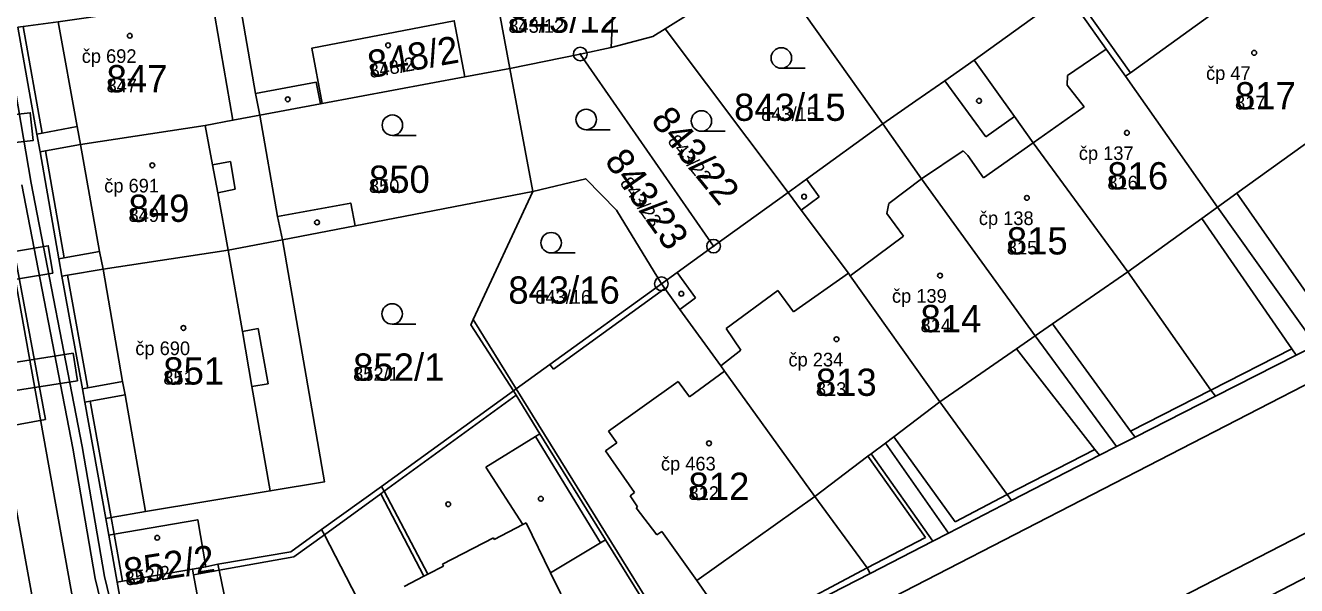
# Model space of a CAD drawing. Extents: x -763628 to -761565, y -976033 to -973833.
# Drawn here: x -762085.7 to -761992.5, y -974693.2 to -974652.1 of the extents above; entities that cross this region are included whole.
import ezdxf

# ---------------------------------------------------------------- set-up
doc = ezdxf.new("R2010")
doc.units = 0
for name, color, linetype in [('KN_cisla parcel 1000', 7, 'Continuous'), ('KN_cisla parcel 500', 7, 'Continuous'), ('KN_cisla popisna 500', 7, 'Continuous'), ('KN_hranice parcel', 7, 'Continuous'), ('KN_vecna bremena', 7, 'Continuous'), ('KN_vnitrni kresba parcel', 7, 'Continuous'), ('KN_znacky bodu BP', 7, 'Continuous'), ('KN_znacky budov', 7, 'Continuous'), ('KN_znacky kultur', 7, 'Continuous')]:
    doc.layers.add(name, color=color, linetype=linetype)

msp = doc.modelspace()

# ---------------------------------------------------------------- linework, layer by layer
at = {"layer": 'KN_hranice parcel'}
for p, q in [((-762042.7, -974653.77), (-762042.3, -974644.72)), ((-762051.82, -974646.23), (-762050.13, -974655.3)), ((-762038.76, -974652.39), (-762031.13, -974647.62)), ((-762022.79, -974659.35), (-762031.13, -974647.62)), ((-762011.38, -974651.3), (-762016.09, -974654.68)), ((-762038.76, -974652.39), (-762029.73, -974664.39)), ((-762044.98, -974654.24), (-762042.7, -974653.77)), ((-762050.13, -974655.3), (-762044.98, -974654.24)), ((-762044.98, -974654.24), (-762035.2, -974668.33)), ((-762053.45, -974655.92), (-762050.13, -974655.3)), ((-762048.46, -974664.33), (-762050.13, -974655.3)), ((-762063.89, -974657.87), (-762053.45, -974655.92)), ((-762068.48, -974658.73), (-762064.03, -974657.9)), ((-762064.03, -974657.9), (-762063.89, -974657.87)), ((-762061.49, -974666.84), (-762048.46, -974664.33)), ((-762029.73, -974664.39), (-762035.2, -974668.33)), ((-761991.04, -974675.58), (-761998.26, -974665.47)), ((-762066.81, -974667.86), (-762061.49, -974666.84)), ((-762079.77, -974688.31), (-762079.55, -974689.53)), ((-762079.55, -974689.53), (-762078.93, -974692.97)), ((-762071.54, -974691.66), (-762072.42, -974691.84))]:
    msp.add_line(p, q, dxfattribs=at)
for points in [[(-762064.03, -974657.9), (-762064.33, -974656.31), (-762068.78, -974657.14), (-762070.06, -974649.78)], [(-761998.26, -974665.47), (-762004.99, -974655.87), (-762006.41, -974653.88), (-762008.25, -974651.3), (-762009.31, -974649.82)], [(-762086.22, -974652.28), (-762085.82, -974652.22), (-762083.26, -974651.87), (-762074.05, -974650.56)], [(-762063.89, -974657.87), (-762064.65, -974653.8), (-762054.22, -974651.8), (-762053.45, -974655.92)], [(-762086.22, -974652.28), (-762084.82, -974660.12), (-762084.59, -974661.41)], [(-762042.7, -974653.77), (-762039.65, -974652.95), (-762038.76, -974652.39)], [(-762016.09, -974654.68), (-762018.24, -974656.21), (-762020.37, -974657.66), (-762022.79, -974659.35)], [(-761998.41, -974679.34), (-761998.73, -974678.89), (-762004.84, -974670.21), (-762011.77, -974660.75), (-762013.14, -974658.83), (-762016.09, -974654.68)], [(-761998.26, -974665.47), (-761996.84, -974664.44), (-761987.89, -974658.01), (-761987.24, -974657.54)], [(-762084.59, -974661.41), (-762084.2, -974661.34), (-762081.62, -974660.88), (-762072.47, -974659.48), (-762070.44, -974659.1), (-762068.48, -974658.73)], [(-762061.49, -974666.84), (-762061.81, -974665.17), (-762067.17, -974666.15), (-762068.48, -974658.73)], [(-762022.79, -974659.35), (-762028.4, -974663.42), (-762029.73, -974664.39)], [(-762005.65, -974683.02), (-762011.63, -974674.91), (-762019.95, -974663.38), (-762022.79, -974659.35)], [(-762084.59, -974661.41), (-762083.2, -974669.25), (-762082.98, -974670.53)], [(-762039.03, -974671.09), (-762042.33, -974665.68), (-762044.58, -974663.39), (-762048.46, -974664.33)], [(-762049.87, -974678.94), (-762053, -974674.09), (-762052.83, -974673.72), (-762048.46, -974664.33)], [(-762013.35, -974686.98), (-762013.67, -974686.55), (-762018.62, -974679.75), (-762025.18, -974670.5), (-762025.3, -974670.32), (-762028.79, -974665.68), (-762029.73, -974664.39)], [(-762082.98, -974670.53), (-762082.58, -974670.46), (-762079.97, -974670.02), (-762070.79, -974668.63), (-762066.81, -974667.86)], [(-762079.77, -974688.31), (-762079.37, -974688.24), (-762076.85, -974687.79), (-762067.71, -974686.28), (-762063.73, -974685.61), (-762066.81, -974667.86)], [(-762035.2, -974668.33), (-762037.86, -974670.25), (-762039.03, -974671.09)], [(-762082.98, -974670.53), (-762081.48, -974678.79), (-762081.31, -974679.78), (-762079.77, -974688.31)], [(-762039.03, -974671.09), (-762047.21, -974677.01), (-762049.68, -974678.8), (-762049.87, -974678.94)], [(-762023.72, -974692.34), (-762023.94, -974691.92), (-762027.78, -974686.7), (-762034.39, -974677.51), (-762034.68, -974677.1), (-762037.68, -974672.97), (-762038.78, -974671.43), (-762039.03, -974671.09)], [(-761998.41, -974679.34), (-761992.49, -974676.32), (-761991.04, -974675.58)], [(-762049.87, -974678.94), (-762059.55, -974685.95), (-762063.94, -974689.12)], [(-762043.13, -974689.86), (-762047.93, -974682.09), (-762049.67, -974679.26), (-762049.87, -974678.94)], [(-762005.65, -974683.02), (-762004.3, -974682.34), (-761998.41, -974679.34)], [(-762013.35, -974686.98), (-762006.91, -974683.67), (-762005.65, -974683.02)], [(-762023.72, -974692.34), (-762019.12, -974689.96), (-762017.98, -974689.37), (-762013.35, -974686.98)], [(-762079.55, -974689.53), (-762079.15, -974689.46), (-762073.02, -974688.39), (-762072.42, -974691.84)], [(-762063.94, -974689.12), (-762066.21, -974690.76), (-762071.54, -974691.66)], [(-762054.13, -974708.07), (-762054.27, -974707.8), (-762060.69, -974695.41), (-762061.34, -974694.14), (-762063.74, -974689.5), (-762063.94, -974689.12)], [(-762051.03, -974706.45), (-762051.16, -974706.19), (-762053.23, -974702.36), (-762046.78, -974699.11), (-762046.11, -974699.33), (-762044.61, -974698.55), (-762044.05, -974696.94), (-762044.94, -974695.52), (-762045.68, -974695.31), (-762047.15, -974692.3), (-762043.49, -974690.08), (-762043.13, -974689.86)], [(-762037.3, -974699.3), (-762037.44, -974699.03), (-762043.13, -974689.86)], [(-762072.42, -974691.84), (-762073.41, -974692.01), (-762078.53, -974692.9), (-762078.93, -974692.97)], [(-762063.09, -974712.69), (-762063.3, -974712.28), (-762065.03, -974709.22), (-762069.14, -974700.49), (-762069.74, -974699.23), (-762070.18, -974698.29), (-762071.45, -974692.1), (-762071.54, -974691.66)], [(-762078.93, -974692.97), (-762078.32, -974696.37), (-762076.4, -974707.16), (-762076.22, -974708.14), (-762074.96, -974715.24), (-762071.48, -974717.01)], [(-762037.3, -974699.3), (-762034.91, -974698.07), (-762033.35, -974697.27), (-762023.72, -974692.34)]]:
    msp.add_lwpolyline(points, dxfattribs=at)
at = {"layer": 'KN_vecna bremena'}
for points in [[(-762089.51, -974682.03), (-762084.2, -974681.04), (-762095.27, -974621.68)], [(-761988.76, -974691.06), (-762016.29, -974705.31), (-762021.52, -974708.2), (-762033, -974714.19), (-762037.98, -974716.84), (-762040.66, -974717.95), (-762050.35, -974722.91), (-762064.2, -974729.69), (-762065.07, -974729.71), (-762065.78, -974729.85), (-762066.52, -974728.18), (-762070.83, -974719.24), (-762071.18, -974718.59), (-762071.95, -974717.95), (-762072.56, -974717.54), (-762074.56, -974716.2), (-762075.21, -974715.43), (-762078.94, -974696.4), (-762079.87, -974692.57), (-762081.5, -974683.02), (-762085.24, -974663.7), (-762087.15, -974652.51)], [(-762091.32, -974661.27), (-762085.08, -974660.57), (-762085.31, -974658.55), (-762091.67, -974659.25)], [(-762085.92, -974663.82), (-762082.18, -974683.14), (-762080.55, -974692.71), (-762079.62, -974696.54), (-762075.87, -974715.75), (-762075.04, -974716.72), (-762073.29, -974717.89), (-762072.37, -974718.51), (-762071.74, -974719.05), (-762071.45, -974719.56), (-762067.16, -974728.48), (-762066.35, -974730.3), (-762066.45, -974730.92), (-762067.22, -974732.38), (-762067.56, -974735.13), (-762067.5, -974735.7), (-762065.34, -974740.35), (-762064.59, -974741.77), (-762063.72, -974743.22), (-762062.71, -974745.45), (-762062.16, -974747.4), (-762060.52, -974750.71)], [(-762087.37, -974670.93), (-762083.66, -974670.31), (-762083.99, -974668.3), (-762087.77, -974668.93)], [(-762087.84, -974679.14), (-762081.85, -974678.2), (-762082.17, -974676.19), (-762088.2, -974677.13)], [(-762086.79, -974697), (-762085.28, -974704.55), (-762084.55, -974708.69), (-762081.89, -974721.59), (-762079.13, -974720.73), (-762076.95, -974720.04), (-762076.45, -974723.59), (-762074.35, -974723.29), (-762075.04, -974718.74), (-762075.21, -974717.28), (-762080.29, -974718.87), (-762082.47, -974708.29), (-762083.02, -974705.18), (-762076.93, -974704.19), (-762077.29, -974702.18), (-762083.39, -974703.18), (-762084.71, -974696.6), (-762086.83, -974684.87)]]:
    msp.add_lwpolyline(points, dxfattribs=at)
at = {"layer": 'KN_vnitrni kresba parcel'}
for p, q in [((-762092.3, -974638.03), (-762078.65, -974713.9)), ((-762004.63, -974655.61), (-761994.48, -974648.27)), ((-762071.99, -974650.16), (-762070.44, -974659.1)), ((-762007.89, -974651.05), (-762004.63, -974655.61)), ((-762081.86, -974659.56), (-762083.26, -974651.87)), ((-762084.43, -974660.05), (-762085.82, -974652.22)), ((-762009.24, -974655.82), (-762006.41, -974653.88)), ((-762009.28, -974656.52), (-762009.24, -974655.82)), ((-762004.63, -974655.61), (-762004.99, -974655.87)), ((-762015.24, -974660.32), (-762018.24, -974656.21)), ((-762008.02, -974658.1), (-762009.28, -974656.52)), ((-762068.48, -974658.73), (-762068.78, -974657.14)), ((-762011.77, -974660.75), (-762008.02, -974658.1)), ((-762084.43, -974660.05), (-762081.86, -974659.56)), ((-762081.62, -974660.88), (-762081.86, -974659.56)), ((-762071.94, -974662.37), (-762072.47, -974659.48)), ((-762013.14, -974658.83), (-762015.24, -974660.32)), ((-762084.82, -974660.12), (-762084.43, -974660.05)), ((-762082.81, -974669.18), (-762084.2, -974661.34)), ((-762080.23, -974668.72), (-762081.62, -974660.88)), ((-762016.9, -974661.33), (-762019.95, -974663.38)), ((-762016.9, -974661.33), (-762016.57, -974661.69)), ((-762015.41, -974663.33), (-762011.77, -974660.75)), ((-762071.94, -974662.37), (-762070.63, -974662.13)), ((-762071.56, -974664.41), (-762071.94, -974662.37)), ((-762070.63, -974662.13), (-762070.29, -974664.14)), ((-762016.57, -974661.69), (-762015.41, -974663.33)), ((-762071.56, -974664.41), (-762070.29, -974664.14)), ((-762027.46, -974664.72), (-762028.4, -974663.42)), ((-762019.95, -974663.38), (-762022.35, -974665.21)), ((-762070.79, -974668.63), (-762071.56, -974664.41)), ((-762028.79, -974665.68), (-762027.46, -974664.72)), ((-761989.89, -974674.41), (-761996.84, -974664.44)), ((-762070.28, -974718.91), (-761967.13, -974665.79)), ((-762022.35, -974665.21), (-762022.49, -974665.93)), ((-762022.49, -974665.93), (-762021.27, -974667.6)), ((-761998.26, -974665.47), (-761999.41, -974666.29)), ((-762066.81, -974667.86), (-762067.17, -974666.15)), ((-761999.41, -974666.29), (-762004.84, -974670.21)), ((-761999.41, -974666.29), (-761992.81, -974675.87)), ((-762021.27, -974667.6), (-762025.18, -974670.5)), ((-762080.23, -974668.72), (-762082.81, -974669.18)), ((-762079.97, -974670.02), (-762080.23, -974668.72)), ((-762069.75, -974674.58), (-762070.79, -974668.63)), ((-762082.81, -974669.18), (-762083.2, -974669.25)), ((-762081.09, -974678.72), (-762082.58, -974670.46)), ((-762078.53, -974678.26), (-762079.97, -974670.02)), ((-762036.52, -974672.11), (-762037.86, -974670.25)), ((-762025.3, -974670.32), (-762029.35, -974673.14)), ((-762010.34, -974674.02), (-762004.84, -974670.21)), ((-762038.78, -974671.43), (-762046.93, -974677.34)), ((-762030.5, -974671.58), (-762034.28, -974674.38)), ((-762029.35, -974673.14), (-762030.5, -974671.58)), ((-762037.68, -974672.97), (-762036.52, -974672.11)), ((-762069.75, -974674.58), (-762068.6, -974674.38)), ((-762068.6, -974674.38), (-762067.86, -974678.42)), ((-762052.83, -974673.72), (-762049.68, -974678.8)), ((-762034.28, -974674.38), (-762033.21, -974675.97)), ((-762011.63, -974674.91), (-762010.34, -974674.02)), ((-762004.63, -974681.89), (-762010.34, -974674.02)), ((-762069.05, -974678.62), (-762069.75, -974674.58)), ((-762012.99, -974675.85), (-762011.63, -974674.91)), ((-762033.21, -974675.97), (-762034.68, -974677.1)), ((-762012.99, -974675.85), (-762018.62, -974679.75)), ((-762007.24, -974683.24), (-762012.99, -974675.85)), ((-761998.73, -974678.89), (-761992.81, -974675.87)), ((-761992.81, -974675.87), (-761992.49, -974676.32)), ((-762047.21, -974677.01), (-762046.93, -974677.34)), ((-762034.39, -974677.51), (-762036.97, -974679.38)), ((-762081.09, -974678.72), (-762081.48, -974678.79)), ((-762078.53, -974678.26), (-762081.09, -974678.72)), ((-762078.35, -974679.24), (-762078.53, -974678.26)), ((-762067.86, -974678.42), (-762069.05, -974678.62)), ((-762067.71, -974686.28), (-762069.05, -974678.62)), ((-762049.68, -974678.8), (-762037.19, -974698.9)), ((-762037.81, -974678.26), (-762042.9, -974681.91)), ((-762036.97, -974679.38), (-762037.81, -974678.26)), ((-762004.63, -974681.89), (-761998.73, -974678.89)), ((-762080.91, -974679.71), (-762081.31, -974679.78)), ((-762078.35, -974679.24), (-762080.91, -974679.71)), ((-762079.37, -974688.24), (-762080.91, -974679.71)), ((-762076.85, -974687.79), (-762078.35, -974679.24)), ((-762059.36, -974686.31), (-762049.67, -974679.26)), ((-762021.99, -974682.31), (-762018.62, -974679.75)), ((-762042.9, -974681.91), (-762042.29, -974682.75)), ((-762004.3, -974682.34), (-762004.63, -974681.89)), ((-762051.9, -974684.54), (-762048.26, -974682.29)), ((-762048.26, -974682.29), (-762047.93, -974682.09)), ((-762043.49, -974690.08), (-762048.26, -974682.29)), ((-762042.29, -974682.75), (-762043.13, -974683.33)), ((-762023.64, -974683.56), (-762022.6, -974682.77)), ((-762022.6, -974682.77), (-762021.99, -974682.31)), ((-762017.98, -974689.37), (-762022.6, -974682.77)), ((-762021.99, -974682.31), (-762017.49, -974688.55)), ((-762043.13, -974683.33), (-762040.99, -974686.4)), ((-762027.78, -974686.7), (-762023.88, -974683.74)), ((-762023.64, -974683.56), (-762023.88, -974683.74)), ((-762023.88, -974683.74), (-762019.67, -974689.69)), ((-762019.12, -974689.96), (-762023.64, -974683.56)), ((-762013.67, -974686.55), (-762007.24, -974683.24)), ((-762007.24, -974683.24), (-762006.91, -974683.67)), ((-762049.2, -974688.75), (-762051.9, -974684.54)), ((-762063.74, -974689.5), (-762059.61, -974686.49)), ((-762059.61, -974686.49), (-762059.36, -974686.31)), ((-762059.61, -974686.49), (-762056.44, -974692.53)), ((-762059.55, -974685.95), (-762059.36, -974686.31)), ((-762059.36, -974686.31), (-762056.16, -974692.39)), ((-762040.99, -974686.4), (-762041.33, -974686.64)), ((-762013.67, -974686.55), (-762017.49, -974688.55)), ((-761987.98, -974687.41), (-762064.87, -974726.96)), ((-762041.33, -974686.64), (-762040.77, -974687.44)), ((-762040.77, -974687.44), (-762040.89, -974687.53)), ((-762040.89, -974687.53), (-762039.36, -974689.51)), ((-762036.43, -974692.86), (-762027.78, -974686.7)), ((-762079.37, -974688.24), (-762079.15, -974689.46)), ((-762051.28, -974689.84), (-762049.2, -974688.75)), ((-762048.95, -974688.62), (-762049.2, -974688.75)), ((-762047.15, -974692.3), (-762048.95, -974688.62)), ((-762039.36, -974689.51), (-762039, -974689.25)), ((-762039, -974689.25), (-762036.43, -974692.86)), ((-762079.15, -974689.46), (-762078.53, -974692.9)), ((-762065.97, -974691.12), (-762063.74, -974689.5)), ((-762051.35, -974689.72), (-762055.07, -974691.66)), ((-762051.28, -974689.84), (-762051.35, -974689.72)), ((-762019.67, -974689.69), (-762023.94, -974691.92)), ((-762071.45, -974692.1), (-762065.97, -974691.12)), ((-762073.33, -974692.44), (-762073.41, -974692.01)), ((-762073.33, -974692.44), (-762071.45, -974692.1)), ((-762056.16, -974692.39), (-762055.01, -974691.79)), ((-762055.07, -974691.66), (-762055.01, -974691.79)), ((-762023.94, -974691.92), (-762033.53, -974697.01)), ((-762072.79, -974695.38), (-762073.33, -974692.44)), ((-762056.44, -974692.53), (-762057.9, -974693.29)), ((-762056.16, -974692.39), (-762056.44, -974692.53)), ((-762036.43, -974692.86), (-762033.53, -974697.01))]:
    msp.add_line(p, q, dxfattribs=at)
at = {"layer": 'KN_znacky bodu BP'}
for centre, radius in [((-762044.98, -974654.24), 0.5), ((-762044.98, -974654.24), 0.0303), ((-762035.2, -974668.33), 0.5), ((-762035.2, -974668.33), 0.0303), ((-762039.03, -974671.09), 0.5), ((-762039.03, -974671.09), 0.0303)]:
    msp.add_circle(centre, radius, dxfattribs=at)
at = {"layer": 'KN_znacky budov'}
for centre in [(-762078.007, -974652.899), (-762059.067, -974653.599), (-761995.567, -974654.149), (-762066.427, -974657.559), (-762015.737, -974657.669), (-762004.897, -974660.019), (-762076.357, -974662.399), (-762028.567, -974664.699), (-762012.227, -974664.789), (-762064.277, -974666.589), (-762018.597, -974670.489), (-762037.567, -974671.819), (-762074.077, -974674.329), (-762026.187, -974675.159), (-762035.537, -974682.789), (-762054.657, -974687.259), (-762047.867, -974686.859), (-762075.997, -974689.719)]:
    msp.add_circle(centre, 0.175, dxfattribs=at)
at = {"layer": 'KN_znacky kultur'}
for p, q in [((-762030.233, -974655.28), (-762028.483, -974655.28)), ((-762058.753, -974660.21), (-762057.003, -974660.21)), ((-762044.543, -974659.79), (-762042.793, -974659.79)), ((-762036.093, -974659.9), (-762034.343, -974659.9)), ((-762047.113, -974668.83), (-762045.363, -974668.83)), ((-762058.773, -974674.05), (-762057.023, -974674.05))]:
    msp.add_line(p, q, dxfattribs=at)
for centre in [(-762030.233, -974654.53), (-762044.543, -974659.04), (-762036.093, -974659.15), (-762058.753, -974659.46), (-762047.113, -974668.08), (-762058.773, -974673.3)]:
    msp.add_circle(centre, 0.75, dxfattribs=at)

# ---------------------------------------------------------------- texts
at = {"layer": 'KN_cisla parcel 1000'}
for s, p in [('843/12', (-762050.25, -974652.68)), ('847', (-762079.71, -974657.05)), ('817', (-761996.97, -974658.3)), ('843/15', (-762033.699, -974659.14)), ('850', (-762060.47, -974664.42)), ('816', (-762006.33, -974664.17)), ('849', (-762078.1, -974666.55)), ('815', (-762013.7, -974668.94)), ('843/16', (-762050.255, -974672.55)), ('814', (-762020.03, -974674.64)), ('852/1', (-762061.63, -974678.2)), ('851', (-762075.55, -974678.48)), ('813', (-762027.7, -974679.31)), ('812', (-762037.04, -974686.94))]:
    msp.add_text(s, height=2, dxfattribs=at).set_placement(p)
for s, rotation, p in [('848/2', 10, (-762060.365, -974656.007)), ('843/22', 309, (-762039.871, -974659.121)), ('843/23', 305, (-762043.248, -974662.079)), ('852/2', 9, (-762078.272, -974693.24))]:
    msp.add_text(s, height=2, rotation=rotation, dxfattribs=at).set_placement(p)
at = {"layer": 'KN_cisla parcel 500'}
for s, p in [('843/12', (-762050.25, -974652.68)), ('847', (-762079.71, -974657.05)), ('817', (-761996.97, -974658.3)), ('843/15', (-762031.715, -974659.14)), ('816', (-762006.33, -974664.17)), ('850', (-762060.47, -974664.42)), ('849', (-762078.1, -974666.55)), ('815', (-762013.7, -974668.94)), ('843/16', (-762048.272, -974672.55)), ('814', (-762020.03, -974674.64)), ('852/1', (-762061.63, -974678.2)), ('851', (-762075.55, -974678.48)), ('813', (-762027.7, -974679.31)), ('812', (-762037.04, -974686.94))]:
    msp.add_text(s, height=1, dxfattribs=at).set_placement(p)
for s, rotation, p in [('848/2', 10, (-762060.365, -974656.007)), ('843/22', 309, (-762038.623, -974660.662)), ('843/23', 305, (-762042.11, -974663.703)), ('852/2', 9, (-762078.272, -974693.24))]:
    msp.add_text(s, height=1, rotation=rotation, dxfattribs=at).set_placement(p)
at = {"layer": 'KN_cisla popisna 500'}
for s, p in [('čp 692', (-762081.531, -974654.891)), ('čp 47', (-761999.091, -974656.141)), ('čp 137', (-762008.421, -974662.011)), ('čp 691', (-762079.881, -974664.391)), ('čp 138', (-762015.751, -974666.781)), ('čp 139', (-762022.121, -974672.481)), ('čp 690', (-762077.601, -974676.321)), ('čp 234', (-762029.711, -974677.151)), ('čp 463', (-762039.061, -974684.781))]:
    msp.add_text(s, height=1, dxfattribs=at).set_placement(p)

doc.saveas('drawing.dxf')
